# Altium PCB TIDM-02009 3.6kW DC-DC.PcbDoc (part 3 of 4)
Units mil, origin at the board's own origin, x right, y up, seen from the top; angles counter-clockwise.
Board outline 11220.47 x 8463 mil, 4 copper layers (Top Layer, Signal Layer 1, Signal Layer 2, Bottom Layer), stack 109.77 mil thick; 298 components, 250 nets, 959 pads, 2937 vias.
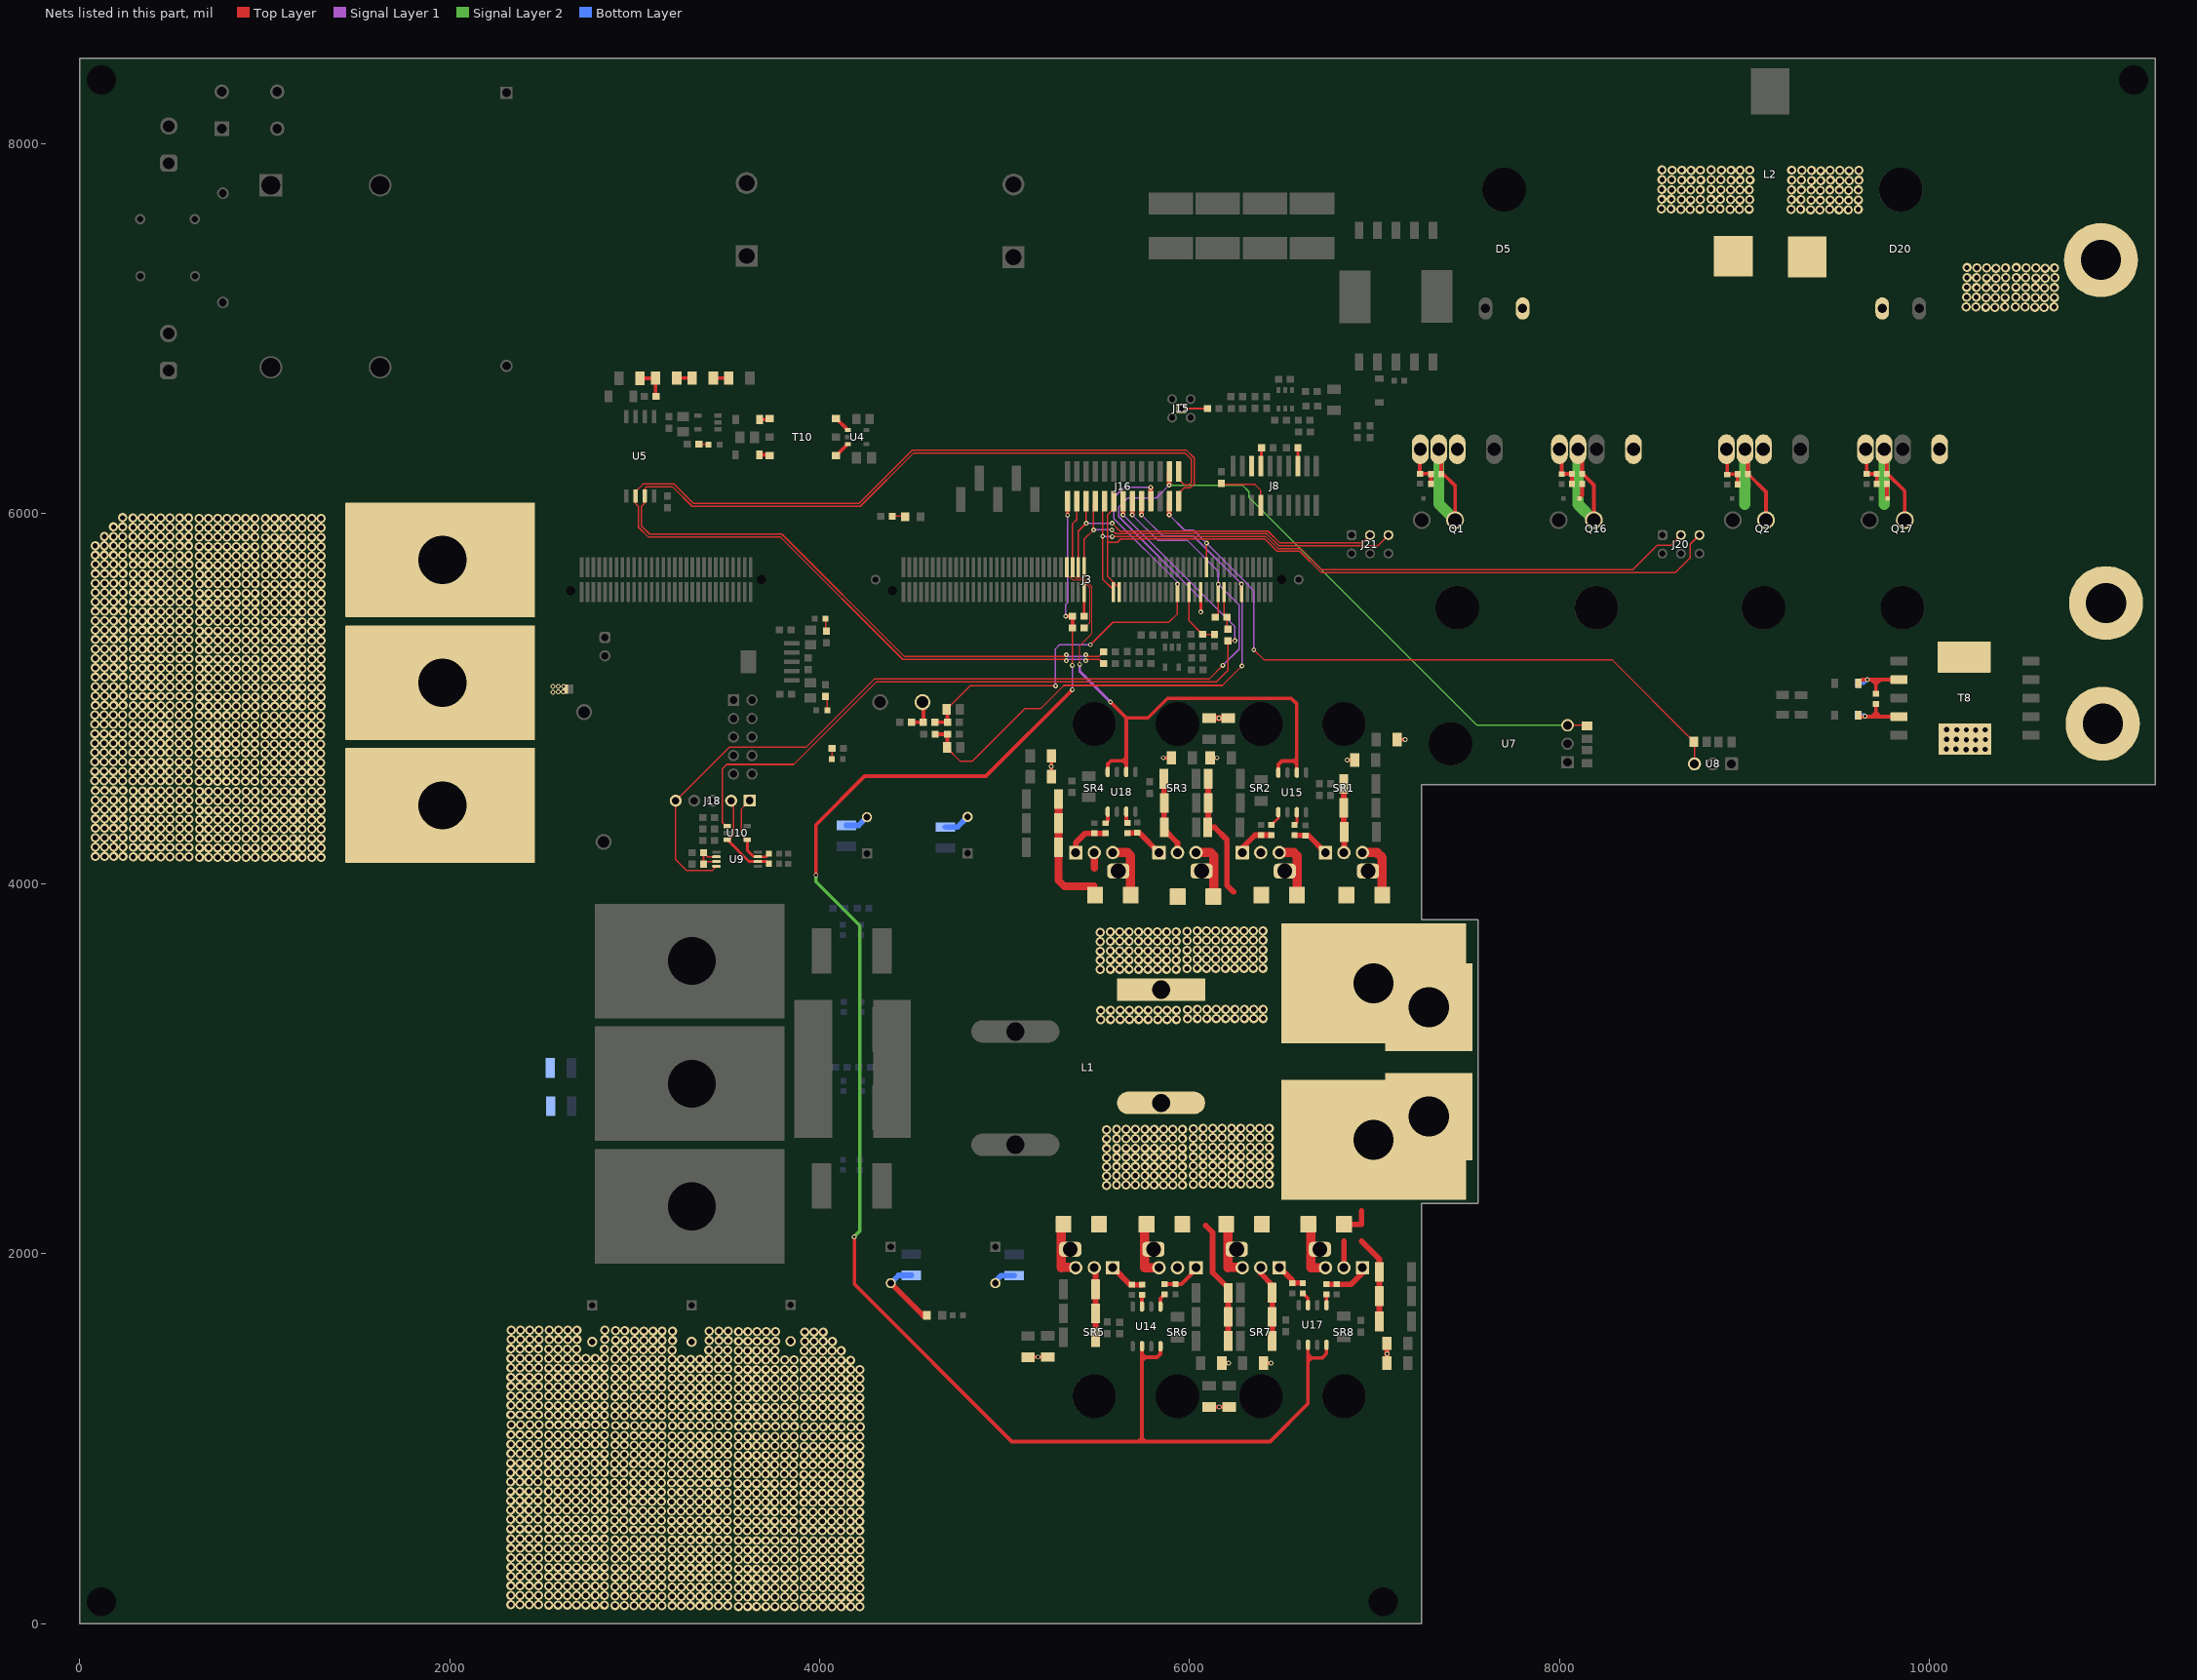
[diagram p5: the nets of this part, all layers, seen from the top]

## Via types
v1: diameter 50, hole 28, Top Layer to Bottom Layer, 2769 vias
v2: diameter 26, hole 12, Top Layer to Bottom Layer, 96 vias
v3: diameter 26, hole 16, Top Layer to Bottom Layer, 49 vias
v4: diameter 36, hole 20, Top Layer to Bottom Layer, 14 vias
v5: diameter 34, hole 16, Top Layer to Bottom Layer, tented both sides, 6 vias
v6: diameter 40, hole 20, Top Layer to Bottom Layer, 2 vias
v7: diameter 50, hole 30, Top Layer to Bottom Layer, 1 vias

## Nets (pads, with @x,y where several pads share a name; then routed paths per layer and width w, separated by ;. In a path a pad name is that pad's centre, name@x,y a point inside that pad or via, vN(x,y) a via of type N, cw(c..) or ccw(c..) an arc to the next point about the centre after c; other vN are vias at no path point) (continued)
NetD5_2: D5.2 D20.1 L2.2 pad.2@10926,7372 T8.11
  other v1: 10354,7116 10620,7116 10304,7117 10570,7117 10407,7118 10673,7118 10198,7119 10250,7119 10464,7119 10516,7119 10356,7168 10622,7168 10306,7169 10572,7169 10409,7170 10675,7170 10200,7171 10252,7171 10466,7171 10518,7171 10356,7222 10622,7222 10254,7223 10306,7223 10408,7223 10520,7223 10572,7223 10674,7223 10200,7225 10466,7225 10358,7274 10624,7274 10308,7275 10574,7275 10411,7276 10677,7276 10202,7277 10254,7277 10468,7277 10520,7277 10358,7328 10624,7328 10256,7329 10308,7329 10410,7329 10522,7329 10574,7329 10676,7329 10202,7331 10468,7331 9407,7643 9561,7643 9357,7644 9511,7644 9460,7645 9614,7645 9251,7646 9303,7646 9409,7695 9563,7695 9359,7696 9513,7696 9462,7697 9616,7697 9253,7698 9305,7698 9409,7749 9563,7749 9307,7750 9359,7750 9461,7750 9513,7750 9615,7750 9253,7752 9411,7801 9565,7801 9361,7802 9515,7802 9464,7803 9618,7803 9255,7804 9307,7804 9411,7855 9565,7855 9309,7856 9361,7856 9463,7856 9515,7856 9617,7856 9255,7858
NetD6_1: D6.1 D7.1 D8.1 D9.1 L1.1 pad.4 R27.1 R28.1 R29.1 R30.1 R31.1 R32.1 R33.1 R34.1 R35.1 R36.1 R37.1 R38.1 SR1.2 SR2.2 SR3.2 SR4.2 | length 2226.5
  Top Layer w30: R33.1@5861.77,4567 5861.77,4437.87 R34.1@5862.64,4437 R35.1@5862.64,4304.73 5862.64,4293.36 5934.48,4221.52 SR3.2@5934.48,4168.79 ; R30.1@6100.44,4566.97 R31.1@6100.44,4436 6100.44,4306.17 R32.1@6099,4304.73 6135.27,4304.73 6202,4238 6202,3992 6238,3956 ; R29.1@6832.81,4539.62 R28.1@6832.81,4409.62 6832.81,4283 R27.1@6836.2,4279.62 6836.2,4170.7 SR1.2@6834.28,4168.79
  Top Layer w40: R38.1@5291.14,4457.45 R37.1@5291.14,4327.45 R36.1@5291.14,4197.45 5291.14,4018.86 5324,3986 5483,3986 ; D9.1@5480.21,3938.79 D9.1@5488.13,3938.79 ; 5484.58,4086 SR4.2@5484.58,4168.79
  other v1: 5519,3264.5 5573,3266.5 5624,3266.5 5675,3266.5 5726,3266.5 5776,3266.5 5827,3266.5 5878,3266.5 5929,3266.5 5988,3269.5 6042,3271.5 6093,3271.5 6144,3271.5 6195,3271.5 6245,3271.5 6296,3271.5 6347,3271.5 6398,3271.5 5519,3314.25 5573,3316.25 5624,3316.25 5675,3316.25 5726,3316.25 5776,3316.25 5827,3316.25 5878,3316.25 5929,3316.25 5988,3319.25 6042,3321.25 6093,3321.25 6144,3321.25 6195,3321.25 6245,3321.25 6296,3321.25 6347,3321.25 6398,3321.25 5517,3536 5571,3538 5622,3538 5673,3538 5724,3538 5774,3538 5825,3538 5876,3538 5927,3538 5986,3541 6040,3543 6091,3543 6142,3543 6193,3543 6243,3543 6294,3543 6345,3543 6396,3543 5517,3585.75 5571,3587.75 5622,3587.75 5673,3587.75 5724,3587.75 5774,3587.75 5825,3587.75 5876,3587.75 5927,3587.75 5986,3590.75 6040,3592.75 6091,3592.75 6142,3592.75 6193,3592.75 6243,3592.75 6294,3592.75 6345,3592.75 6396,3592.75 5517,3635.5 5571,3637.5 5622,3637.5 5673,3637.5 5724,3637.5 5774,3637.5 5825,3637.5 5876,3637.5 5927,3637.5 5986,3640.5 6040,3642.5 6091,3642.5 6142,3642.5 6193,3642.5 6243,3642.5 6294,3642.5 6345,3642.5 6396,3642.5 5517,3687.5 5571,3689.5 5622,3689.5 5673,3689.5 5724,3689.5 5774,3689.5 5825,3689.5 5876,3689.5 5927,3689.5 5986,3692.5 6040,3694.5 6091,3694.5 6142,3694.5 6193,3694.5 6243,3694.5 6294,3694.5 6345,3694.5 6396,3694.5 5517,3737.25 5571,3739.25 5622,3739.25 5673,3739.25 5724,3739.25 5774,3739.25 5825,3739.25 5876,3739.25 5927,3739.25 5986,3742.25 6040,3744.25 6091,3744.25 6142,3744.25 6193,3744.25 6243,3744.25 6294,3744.25 6345,3744.25 6396,3744.25
NetD10_2: D10.2 D11.2 D12.2 D13.2 L1.3 pad.3 R44.1 R45.1 R46.1 R47.1 R48.1 R49.1 R50.1 R51.1 R52.1 R53.1 R54.1 R55.1 SR5.2 SR6.2 SR7.2 SR8.2 | length 2235.2
  Top Layer w30: SR5.2@5485.1,1926.05 5491.52,1919.62 R46.1@5491.52,1807.96 R45.1@5491.52,1677.61 R44.1@5491.52,1547.61 ; 6087,2152 6124.52,2114.48 6124.52,1898.44 6208.34,1814.62 R47.1@6208.34,1788.61 R48.1@6208.34,1658.61 R49.1@6208.34,1528.61 ; SR7.2@6384.9,1926.05 6384.9,1892.5 6446.52,1830.88 R50.1@6446.52,1788.96 R51.1@6446.52,1658.61 R52.1@6446.52,1528.61 ; D13.2@6834.68,2158.79 6929.21,2158.79 6929.21,2231.21 ; SR8.2@6834.8,1924.95 6835.2,1925.35 6835.2,2067.23 ; 6929.73,2067.23 7026.01,1970.95 R53.1@7026.01,1659.07
  other v1: 5551,2369.5 5605,2371.5 5656,2371.5 5707,2371.5 5758,2371.5 5808,2371.5 5859,2371.5 5910,2371.5 5961,2371.5 6020,2374.5 6074,2376.5 6125,2376.5 6176,2376.5 6227,2376.5 6277,2376.5 6328,2376.5 6379,2376.5 6430,2376.5 5551,2419.25 5605,2421.25 5656,2421.25 5707,2421.25 5758,2421.25 5808,2421.25 5859,2421.25 5910,2421.25 5961,2421.25 6020,2424.25 6074,2426.25 6125,2426.25 6176,2426.25 6227,2426.25 6277,2426.25 6328,2426.25 6379,2426.25 6430,2426.25 5551,2469 5605,2471 5656,2471 5707,2471 5758,2471 5808,2471 5859,2471 5910,2471 5961,2471 6020,2474 6074,2476 6125,2476 6176,2476 6227,2476 6277,2476 6328,2476 6379,2476 6430,2476 5551,2518.75 5605,2520.75 5656,2520.75 5707,2520.75 5758,2520.75 5808,2520.75 5859,2520.75 5910,2520.75 5961,2520.75 6020,2523.75 6074,2525.75 6125,2525.75 6176,2525.75 6227,2525.75 6277,2525.75 6328,2525.75 6379,2525.75 6430,2525.75 5551,2568.5 5605,2570.5 5656,2570.5 5707,2570.5 5758,2570.5 5808,2570.5 5859,2570.5 5910,2570.5 5961,2570.5 6020,2573.5 6074,2575.5 6125,2575.5 6176,2575.5 6227,2575.5 6277,2575.5 6328,2575.5 6379,2575.5 6430,2575.5 5551,2620.5 5605,2622.5 5656,2622.5 5707,2622.5 5758,2622.5 5808,2622.5 5859,2622.5 5910,2622.5 5961,2622.5 6020,2625.5 6074,2627.5 6125,2627.5 6176,2627.5 6227,2627.5 6277,2627.5 6328,2627.5 6379,2627.5 6430,2627.5 5551,2670.25 5605,2672.25 5656,2672.25 5707,2672.25 5758,2672.25 5808,2672.25 5859,2672.25 5910,2672.25 5961,2672.25 6020,2675.25 6074,2677.25 6125,2677.25 6176,2677.25 6227,2677.25 6277,2677.25 6328,2677.25 6379,2677.25 6430,2677.25
NetD14_2: D14.2 D15.1 R43.1 T8.4 | length 407.4
  Top Layer w20: D14.2@9615.47,4911 9622.47,4904 9686,4904 ; R43.1@9710,4972.44 9710,4928 ; 9743,4904 9734,4904 ; T8.4@9835.19,4904 9734,4904 ; 9686,4904 9711,4904 ; 9686,4904 9710,4928 ; 9710,4928 9710,4905 9711,4904 ; 9710,4928 9734,4904 ; 9711,4904 9734,4904
  Bottom Layer w20: D15.1@9614.47,4911 9645,4911 v3(9651,4905)
NetD16_2: D16.2 D17.1 R43.2 T8.2 | length 443.2
  Top Layer w20: D16.2@9615.47,5084 9635.47,5104 v3(9663,5104) ; v3@9665,5104 v3(9663,5104) ; R43.2@9710,5027.56 9710,5079 ; 9744,5104 9735,5104 ; T8.2@9835.19,5104 9735,5104 ; v3(9663,5104) 9685,5104 ; 9685,5104 9713,5104 ; 9685,5104 9710,5079 ; 9710,5079 9710,5101 9713,5104 ; 9710,5079 9735,5104 ; 9713,5104 9735,5104
  Bottom Layer w20: D17.1@9615.47,5084 9643,5084 v3(9663,5104)
NetD18_2: D18.2 R69.1 | length 83.8
  Top Layer w20: D18.2@8106.31,6084 8121.56,6099.25 R69.1@8121.56,6161.44
NetD19_2: D19.2 R70.1 | length 78.4
  Top Layer w20: R70.1@9770.12,6161 9770.12,6087.5 D19.2@9773.61,6084
NetD21_2: D21.2 T10.6 | length 55.8
  Top Layer w20: D21.2@3674.47,6318 3726,6318 T10.6@3729,6315
NetD22_2: D22.2 R95.1 | length 70.7
  Top Layer w8: R95.1@4392.5,5987 4460.32,5987 D22.2@4462.32,5985
NetD23_1: D23.1 R75.1 | length 53.1
  Top Layer w8: R75.1@3347,6376 3397.25,6376 D23.1@3399.25,6374
NetD24_1: D24.1 R96.1 | length 57
  Top Layer w8: D24.1@4065.98,4675.03 R96.1@4065.98,4732
NetD25_1: D25.1 R88.1 | length 68.9
  Top Layer w8: D25.1@4032.53,5433 4032.53,5368.97 R88.1@4036,5365.5
NetD26_1: D26.1 R140.1 | length 80.5
  Top Layer w8: R140.1@4032,5013.5 4041.53,5003.98 D26.1@4041.53,4937
NetD27_2: D27.2 T10.4 | length 55.6
  Top Layer w20: D27.2@3675.47,6510 3724,6510 T10.4@3729,6515
NetJ3_18: J3.18 R91.1 R92.1 | length 209.3
  Top Layer w8: J3.18@6186.04,5577.14 6186.04,5456.46 R91.1@6201.5,5441 6201.5,5382 R92.1@6207,5376.5
NetJ3_58: J3.58 R12.1 | length 131.2
  Top Layer w15: R12.1@5430,5446 5430,5577.01 J3.58@5430.13,5577.14
NetJ3_63: J3.63 R87.2 | length 422.3
  Top Layer w6: J3.63@5335.65,5711 5335.65,5674.35 5368,5642 5419,5642 5460.56,5600.44 5460.56,5413.57 R87.2@5429.99,5383
NetJ8_5: J8.5 R16.2 | length 99.2
  Top Layer w15: J8.5@6585,6258 6585.5,6258.5 R16.2@6585.5,6357
NetJ8_13: J8.13 R39.2 | length 100.2
  Top Layer w15: J8.13@6385,6258 6388.01,6261.01 R39.2@6388.01,6357
NetJ8_14: J8.14 R19.1 | length 311.5
  Top Layer w8: R19.1@6171,6164.5 6177.37,6158.13 6353.87,6158.13 6385,6127 J8.14@6385,6045.01
NetJ15_1: J15.1 R59.2 | length 140.9
  Top Layer w10: J15.1@5955,6570 5956,6569 R59.2@6095.5,6569
NetJ18_1: J18.1 R10.1 U9.3 U10.4 | length 442.8
  Top Layer w8: U10.4@3609.13,4237.6 3603.4,4237.6 3576,4265 3576,4403 J18.1@3622,4449
  Top Layer w15: U10.4@3609.13,4237.6 3609.13,4179.83 3640.83,4148.14 3663.86,4148.14 U9.3@3666.2,4145.8 3708.24,4145.8 R10.1@3725.44,4163
NetJ18_2: J18.2 R13.1 U9.2 U10.3 | length 513.6
  Top Layer w8: U10.3@3500.87,4237.6 3510.58,4237.6 3534,4261.02 3534,4437 J18.2@3522,4449
  Top Layer w15: U10.3@3500.87,4237.6 3618.26,4120.2 U9.2@3666.2,4120.2 3712.8,4120.2 R13.1@3725,4108
NetL2_1: L2.1 Q1.2 Q16.1
  other v1: 8706,7645 8972,7645 8656,7646 8922,7646 8759,7647 9025,7647 8550,7648 8602,7648 8816,7648 8868,7648 8708,7697 8974,7697 8658,7698 8924,7698 8761,7699 9027,7699 8552,7700 8604,7700 8818,7700 8870,7700 8708,7751 8974,7751 8606,7752 8658,7752 8760,7752 8872,7752 8924,7752 9026,7752 8552,7754 8818,7754 8710,7803 8976,7803 8660,7804 8926,7804 8763,7805 9029,7805 8554,7806 8606,7806 8820,7806 8872,7806 8710,7857 8976,7857 8608,7858 8660,7858 8762,7858 8874,7858 8926,7858 9028,7858 8554,7860 8820,7860
NetQ1_4: Q1.4 R21.2 R23.2 R25.2 | length 247.8
  Top Layer w20: Q1.4@7247,6348.89 7245,6346.89 R21.2@7245,6217.12 7301.32,6217.12 R25.2@7304.44,6214 ; R23.2@7304.44,6161 R25.2@7304.44,6214 ; R25.2@7305.44,6215 R25.2@7304.44,6214
NetQ2_2: pad.1@10954,5518 Q2.2 Q17.1
NetQ2_4: Q2.4 R22.2 R24.2 R26.2 | length 251.5
  Top Layer w20: Q2.4@8901.89,6348.89 8906,6344.78 R22.2@8906,6212 8909,6215 R26.2@8962.44,6215 8961.88,6214.44 R24.2@8961.88,6160
NetQ16_4: Q16.4 R64.2 R69.2 R71.2 | length 249.7
  Top Layer w20: Q16.4@7999.44,6348.89 8011,6337.34 R64.2@8011,6214.56 8012.44,6216 R71.2@8066.44,6216 R69.2@8066.44,6161.44
NetQ17_4: Q17.4 R65.2 R70.2 R72.2 | length 244.9
  Top Layer w20: Q17.4@9654.33,6348.89 9660,6343.23 R65.2@9660,6216.56 9660.56,6216 R72.2@9715,6216 R70.2@9715,6161
NetR40_1: R40.1 R57.2 TP3.1 | length 176.6
  Top Layer w20: R40.1@4495.5,4873 R57.2@4561.01,4873 4561.01,4976.99 TP3.1@4556,4982
NetR76_2: R76.2 R77.1 | length 83.8
  Top Layer w20: R77.1@3425.17,6734 R76.2@3509,6734
NetR77_2: R77.2 R78.1 | length 83.8
  Top Layer w20: R78.1@3227.17,6734 R77.2@3311,6734
NetR78_2: R78.2 R79.1 R80.2 | length 184.8
  Top Layer w20: R80.2@3029.09,6733 3112,6733 R78.2@3113,6734 3113,6638.5 R79.1@3116.5,6635
NetR89_1: R89.1 R90.2 U9.6 U9.7 | length 215.7
  Top Layer w8: U9.7@3441.8,4120.2 3386.7,4120.2 R90.2@3372.5,4106 R89.1@3372.5,4168 3394.7,4145.8 U9.6@3441.8,4145.8
NetR152_1: R152.1 U14.7 | length 63
  Top Layer w20: U14.7@5742.47,1714.35 5742.47,1775.26 R152.1@5743.92,1776.72
NetR153_1: R153.1 U15.7 | length 74.3
  Top Layer w15: R153.1@6567.19,4316.98 6579.39,4329.18 U15.7@6579.39,4386.23
NetR155_1: R155.1 U14.5 | length 74.1
  Top Layer w20: U14.5@5842.47,1714.35 5842.47,1758.06 R155.1@5863.92,1779.52
NetR156_1: R156.1 U15.5 | length 83.7
  Top Layer w15: R156.1@6441.7,4318.16 6479.39,4355.86 U15.5@6479.39,4386.23
NetR168_1: R168.1 U17.7 | length 76.6
  Top Layer w20: R168.1@6611.76,1786.44 6639.91,1758.29 U17.7@6639.91,1721.52
NetR169_1: R169.1 U18.7 | length 63.5
  Top Layer w15: R169.1@5657.42,4335.7 R169.1@5664,4329.12
  Top Layer w20: R169.1@5657.42,4335.7 U18.7@5657.42,4389.88
NetR170_1: R170.1 U17.5 | length 58.5
  Top Layer w20: R170.1@6738.74,1779.55 6739.91,1778.38 U17.5@6739.91,1721.52
NetR171_1: R171.1 U18.5 | length 67.5
  Top Layer w15: R171.1@5545.22,4327.45 R171.1@5557.42,4339.65
  Top Layer w20: R171.1@5557.42,4339.65 U18.5@5557.42,4389.88
NetT6_1: pad.2@10936,4865 T8.12
  other v1: 10247,4725 10197,4726 10300,4727 10091,4728 10143,4728 10249,4777 10199,4778 10302,4779 10093,4780 10145,4780 10249,4831 10147,4832 10199,4832 10301,4832 10093,4834
NetT10_1: T10.1 U4.3 | length 89.7
  Top Layer w20: T10.1@4089,6315 4090.2,6315 U4.3@4152.8,6377.6
NetT10_3: T10.3 U4.1 | length 89.7
  Top Layer w20: T10.3@4089,6515 4090.2,6515 U4.1@4152.8,6452.4
nTGTRST: J8.15
PGND: C14.2 C15.2 C16.1 C17.1 C18.1 C19.1 C20.1 C21.1 C22.1 C23.1 C24.2 C25.2 C26.2 C27.2 C28.2 C29.2 C30.2 C31.1 C32.1 C33.1 C34.1 C35.1 C36.1 C37.1 C38.1 C44.2 C71.2 C72.2 C86.2 D1.1 D6.2 D7.2 D8.2 D9.2 D10.1 D11.1 D12.1 D13.1 NT1.1 pad.1@1961.56,4423.45 pad.1@1961.56,5086.97 pad.1@1961.56,5750.49 pad.5 SR1.3 SR2.3 SR3.3 SR4.3 SR5.3 SR6.3 SR7.3 SR8.3 T2.1 T3.1 T4.1 | length 4173.7
  Top Layer w20: C31.1@5126.52,1440.27 5127.61,1441.35 v3(5180.56,1441.35) C35.1@5233.52,1441.35 ; C23.1@5252.7,4578.72 v3(5252.7,4634.96) C19.1@5252.7,4691.2 ; v3(5858.21,4680.79) C22.1@5901.3,4680.79 ; C32.1@6105.73,1171.14 v3(6159.82,1171.14) C37.1@6213.91,1171.14 ; C21.1@6111.33,4680.79 v3(6148.79,4680.79) ; C36.1@6174.08,1408.23 v3(6211.73,1408.23) ; C33.1@6399.87,1408.23 v3(6439.73,1408.23) ; v3(6850.79,4668.79) C20.1@6892.22,4668.79 ; C16.1@7122.21,4778.79 v3(7164.79,4778.79)
  Top Layer w30: C27.2@4384.39,1840.69 4558.08,1667 D1.1@4580.32,1667 ; C18.1@6105,4895.09 C17.1@6209,4895.09 ; C38.1@7066.05,1407.69 C34.1@7066.05,1514.69
  Top Layer w50: D10.1@5305.85,2146.51 D10.1@5306.37,2147.03 ; D10.1@5318.12,2158.79 D10.1@5306.37,2147.03 ; SR5.3@5385.1,1926.05 5307.47,1926.05 5306.37,1924.94 D10.1@5306.37,2147.03 ; SR4.3@5584.58,4168.79 5663.33,4168.79 5681.04,4151.08 D9.2@5681.04,3938.79 ; D11.1@5766.95,2158.79 5755.74,2147.58 5756.26,2147.06 5756.26,1924.94 5757.21,1924 SR6.3@5835,1924 ; SR3.3@6033.79,4168.79 SR3.3@6034.48,4168.79 6113.22,4168.79 6130.94,4151.07 D8.2@6130.94,3938.79 ; D12.1@6197.93,2158.79 6206.16,2150.57 6206.16,1924.94 6207.26,1926.05 SR7.3@6284.9,1926.05 ; SR2.3@6484.38,4168.79 6563.12,4168.79 6580.85,4151.06 D7.2@6580.85,3938.79 ; D13.1@6641.77,2158.79 6656.05,2144.5 6656.05,1924.95 SR8.3@6734.8,1924.95 ; SR1.3@6934.28,4168.79 7013.01,4168.79 7040.52,4141.28 D6.2@7040.52,3938.79
  Bottom Layer w20: T2.1@1923,4384.89 T2.1@1961.56,4423.45
  Bottom Layer w30: C86.2@4144,4316 4211.53,4316 C25.2@4255.61,4360.08 ; C27.2@4384.39,1840.69 4426.62,1882.91 C30.2@4496,1882.91 ; C28.2@4680,4307 4745.27,4307 C24.2@4800.06,4361.79 ; C26.2@4940.69,1841.94 4980.67,1881.91 C29.2@5052,1881.91
  other v1: 3917.25,92 3967,92 4016.75,92 4066.5,92 4116.25,92 4168.25,92 4218,92 3560.25,93 3610,93 3659.75,93 3709.5,93 3759.25,93 3811.25,93 3861,93 3202.25,96 3252,96 3301.75,96 3351.5,96 3401.25,96 3453.25,96 3503,96 2997.25,97 3047,97 3096.75,97 3146.5,97 2894.25,98 2944,98 2536.25,101 2586,101 2635.75,101 2685.5,101 2735.25,101 2787.25,101 2837,101 2331.25,102 2381,102 2430.75,102 2480.5,102 3917.25,143 3967,143 4016.75,143 4066.5,143 4116.25,143 4168.25,143 4218,143 3560.25,144 3610,144 3659.75,144 3709.5,144 3759.25,144 3811.25,144 3861,144 3202.25,147 3252,147 3301.75,147 3351.5,147 3401.25,147 3453.25,147 3503,147 2997.25,148 3047,148 3096.75,148 3146.5,148 2894.25,149 2944,149 2536.25,152 2586,152 2635.75,152 2685.5,152 2735.25,152 2787.25,152 2837,152 2331.25,153 2381,153 2430.75,153 2480.5,153 3917.25,194 3967,194 4016.75,194 4066.5,194 4116.25,194 4168.25,194 4218,194 3560.25,195 3610,195 3659.75,195 3709.5,195 3759.25,195 3811.25,195 3861,195 3202.25,198 3252,198 3301.75,198 3351.5,198 3401.25,198 3453.25,198 3503,198 2997.25,199 3047,199 3096.75,199 3146.5,199 2894.25,200 2944,200 2536.25,203 2586,203 2635.75,203 2685.5,203 2735.25,203 2787.25,203 2837,203 2331.25,204 2381,204 2430.75,204 2480.5,204 3917.25,245 3967,245 4016.75,245 4066.5,245 4116.25,245 4168.25,245 4218,245 3560.25,246 3610,246 3659.75,246 3709.5,246 3759.25,246 3811.25,246 3861,246 3202.25,249 3252,249 3301.75,249 3351.5,249 3401.25,249 3453.25,249 3503,249 2997.25,250 3047,250 3096.75,250 3146.5,250 2894.25,251 2944,251 2536.25,254 2586,254 2635.75,254 2685.5,254 2735.25,254 2787.25,254 2837,254 2331.25,255 2381,255 2430.75,255 2480.5,255 3917.25,295 3967,295 4016.75,295 4066.5,295 4116.25,295 4168.25,295 4218,295 3560.25,296 3610,296 3659.75,296 3709.5,296 3759.25,296 3811.25,296 3861,296 3202.25,299 3252,299 3301.75,299 3351.5,299 3401.25,299 3453.25,299 3503,299 2997.25,300 3047,300 3096.75,300 3146.5,300 2894.25,301 2944,301 2536.25,304 2586,304 2635.75,304 2685.5,304 2735.25,304 2787.25,304 2837,304 2331.25,305 2381,305 2430.75,305 2480.5,305 3917.25,346 3967,346 4016.75,346 4066.5,346 4116.25,346 4168.25,346 4218,346 3560.25,347 3610,347 3659.75,347 3709.5,347 3759.25,347 3811.25,347 3861,347 3202.25,350 3252,350 3301.75,350 3351.5,350 3401.25,350 3453.25,350 3503,350 2997.25,351 3047,351 3096.75,351 3146.5,351 2894.25,352 2944,352 2536.25,355 2586,355 2635.75,355 2685.5,355 2735.25,355 2787.25,355 2837,355 2331.25,356 2381,356 2430.75,356 2480.5,356 3917.25,397 3967,397 4016.75,397 4066.5,397 4116.25,397 4168.25,397 4218,397 3560.25,398 3610,398 3659.75,398 3709.5,398 3759.25,398 3811.25,398 3861,398 3202.25,401 3252,401 3301.75,401 3351.5,401 3401.25,401 3453.25,401 3503,401 2997.25,402 3047,402 3096.75,402 3146.5,402 2894.25,403 2944,403 2536.25,406 2586,406 2635.75,406 2685.5,406 2735.25,406 2787.25,406 2837,406 2331.25,407 2381,407 2430.75,407 2480.5,407 3917.25,448 3967,448 4016.75,448 4066.5,448 4116.25,448 4168.25,448 4218,448 3560.25,449 3610,449 3659.75,449 3709.5,449 3759.25,449 3811.25,449 3861,449 3202.25,452 3252,452 3301.75,452 3351.5,452 3401.25,452 3453.25,452 3503,452 2997.25,453 3047,453 3096.75,453 3146.5,453 2894.25,454 2944,454 2536.25,457 2586,457 2635.75,457 2685.5,457 2735.25,457 2787.25,457 2837,457 2331.25,458 2381,458 2430.75,458 2480.5,458 3915.25,502 3965,502 4014.75,502 4064.5,502 4114.25,502 4166.25,502 4216,502 3558.25,503 3608,503 3657.75,503 3707.5,503 3757.25,503 3809.25,503 3859,503 3200.25,506 3250,506 3299.75,506 3349.5,506 3399.25,506 3451.25,506 3501,506 2995.25,507 3045,507 3094.75,507 3144.5,507 2892.25,508 2942,508 2534.25,511 2584,511 2633.75,511 2683.5,511 2733.25,511 2785.25,511 2835,511 2329.25,512 2379,512 2428.75,512 2478.5,512 3915.25,553 3965,553 4014.75,553 4064.5,553 4114.25,553 4166.25,553 4216,553 3558.25,554 3608,554 3657.75,554 3707.5,554 3757.25,554 3809.25,554 3859,554 3200.25,557 3250,557 3299.75,557 3349.5,557 3399.25,557 3451.25,557 3501,557 2995.25,558 3045,558 3094.75,558 3144.5,558 2892.25,559 2942,559 2534.25,562 2584,562 2633.75,562 2683.5,562 2733.25,562 2785.25,562 2835,562 2329.25,563 2379,563 2428.75,563 2478.5,563 3915.25,604 3965,604 4014.75,604 4064.5,604 4114.25,604 4166.25,604 4216,604 3558.25,605 3608,605 3657.75,605 3707.5,605 3757.25,605 3809.25,605 3859,605 3200.25,608 3250,608 3299.75,608 3349.5,608 3399.25,608 3451.25,608 3501,608 2995.25,609 3045,609 3094.75,609 3144.5,609 2892.25,610 2942,610 2534.25,613 2584,613 2633.75,613 2683.5,613 2733.25,613 2785.25,613 2835,613 2329.25,614 2379,614 2428.75,614 2478.5,614 3915.25,655 3965,655 4014.75,655 4064.5,655 4114.25,655 4166.25,655 4216,655 3558.25,656 3608,656 3657.75,656 3707.5,656 3757.25,656 3809.25,656 3859,656 3200.25,659 3250,659 3299.75,659 3349.5,659 3399.25,659 3451.25,659 3501,659 2995.25,660 3045,660 3094.75,660 3144.5,660 2892.25,661 2942,661 2534.25,664 2584,664 2633.75,664 2683.5,664 2733.25,664 2785.25,664 2835,664 2329.25,665 2379,665 2428.75,665 2478.5,665 3915.25,705 3965,705 4014.75,705 4064.5,705 4114.25,705 4166.25,705 4216,705 3558.25,706 3608,706 3657.75,706 3707.5,706 3757.25,706 3809.25,706 3859,706 3200.25,709 3299.75,709 3349.5,709 3399.25,709 3451.25,709 3501,709 2995.25,710 3045,710 3094.75,710 3144.5,710 3251,710 2892.25,711 2942,711 2534.25,714 2633.75,714 2683.5,714 2733.25,714 2785.25,714 2835,714 2329.25,715 2379,715 2428.75,715 2478.5,715 2585,715 3915.25,756 3965,756 4014.75,756 4064.5,756 4114.25,756 4166.25,756 4216,756 3558.25,757 3608,757 3657.75,757 3707.5,757 3757.25,757 3809.25,757 3859,757 3200.25,760 3250,760 3299.75,760 3349.5,760 3399.25,760 3451.25,760 3501,760 2995.25,761 3045,761 3094.75,761 3144.5,761 2892.25,762 2942,762 2534.25,765 2584,765 2633.75,765 2683.5,765 2733.25,765 2785.25,765 2835,765 2329.25,766 2379,766 2428.75,766 2478.5,766 3915.25,807 3965,807 4014.75,807 4064.5,807 4114.25,807 4166.25,807 4216,807 3558.25,808 3608,808 3657.75,808 3707.5,808 3757.25,808 3809.25,808 3859,808 3200.25,811 3250,811 3299.75,811 3349.5,811 3399.25,811 3451.25,811 3501,811 2995.25,812 3045,812 3094.75,812 3144.5,812 2892.25,813 2942,813 2534.25,816 2584,816 2633.75,816 2683.5,816 2733.25,816 2785.25,816 2835,816 2329.25,817 2379,817 2428.75,817 2478.5,817 3915.25,858 3965,858 4014.75,858 4064.5,858 4114.25,858 4166.25,858 4216,858 3558.25,859 3608,859 3657.75,859 3707.5,859 3757.25,859 3809.25,859 3859,859 3200.25,862 3250,862 3299.75,862 3349.5,862 3399.25,862 3451.25,862 3501,862 2995.25,863 3045,863 3094.75,863 3144.5,863 2892.25,864 2942,864 2534.25,867 2584,867 2633.75,867 2683.5,867 2733.25,867 2785.25,867 2835,867 2329.25,868 2379,868 2428.75,868 2478.5,868 3917.25,909 3967,909 4016.75,909 4066.5,909 4116.25,909 4168.25,909 4218,909 3560.25,910 3610,910 3659.75,910 3709.5,910 3759.25,910 3811.25,910 3861,910 3202.25,913 3252,913 3301.75,913 3351.5,913 3401.25,913 3453.25,913 3503,913 2997.25,914 3047,914 3096.75,914 3146.5,914 2894.25,915 2944,915 2536.25,918 2586,918 2635.75,918 2685.5,918 2735.25,918 2787.25,918 2837,918 2331.25,919 2381,919 2430.75,919 2480.5,919 3917.25,960 3967,960 4016.75,960 4066.5,960 4116.25,960 4168.25,960 4218,960 3560.25,961 3610,961 3659.75,961 3709.5,961 3759.25,961 3811.25,961 3861,961 3202.25,964 3252,964 3301.75,964 3351.5,964 3401.25,964 3453.25,964 3503,964 2997.25,965 3047,965 3096.75,965 3146.5,965 2894.25,966 2944,966 2536.25,969 2586,969 2635.75,969 2685.5,969 2735.25,969 2787.25,969 2837,969 2331.25,970 2381,970 2430.75,970 2480.5,970 3917.25,1011 3967,1011 4016.75,1011 4066.5,1011 4116.25,1011 4168.25,1011 4218,1011 3560.25,1012 3610,1012 3659.75,1012 3709.5,1012 3759.25,1012 3811.25,1012 3861,1012 3202.25,1015 3252,1015 3301.75,1015 3351.5,1015 3401.25,1015 3453.25,1015 3503,1015 2997.25,1016 3047,1016 3096.75,1016 3146.5,1016 2894.25,1017 2944,1017 2536.25,1020 2586,1020 2635.75,1020 2685.5,1020 2735.25,1020 2787.25,1020 2837,1020 2331.25,1021 2381,1021 2430.75,1021 2480.5,1021 3919.25,1065 3969,1065 4018.75,1065 4068.5,1065 4118.25,1065 4170.25,1065 4220,1065 3562.25,1066 3612,1066 3661.75,1066 3711.5,1066 3761.25,1066 3813.25,1066 3863,1066 3204.25,1069 3254,1069 3303.75,1069 3353.5,1069 3403.25,1069 3455.25,1069 3505,1069 2999.25,1070 3049,1070 3098.75,1070 3148.5,1070 2896.25,1071 2946,1071 2538.25,1074 2588,1074 2637.75,1074 2687.5,1074 2737.25,1074 2789.25,1074 2839,1074 2333.25,1075 2383,1075 2432.75,1075 2482.5,1075 3917.25,1119 3967,1119 4016.75,1119 4066.5,1119 4116.25,1119 4168.25,1119 4218,1119 3560.25,1120 3610,1120 3659.75,1120 3709.5,1120 3759.25,1120 3811.25,1120 3861,1120 3202.25,1123 3252,1123 3301.75,1123 3351.5,1123 3401.25,1123 3453.25,1123 3503,1123 2997.25,1124 3047,1124 3096.75,1124 3146.5,1124 2894.25,1125 2944,1125 2536.25,1128 2586,1128 2635.75,1128 2685.5,1128 2735.25,1128 2787.25,1128 2837,1128 2331.25,1129 2381,1129 2430.75,1129 2480.5,1129 3917.25,1170 3967,1170 4016.75,1170 4066.5,1170 4116.25,1170 4168.25,1170 4218,1170 3560.25,1171 3610,1171 3659.75,1171 3709.5,1171 3759.25,1171 3811.25,1171 3861,1171 3202.25,1174 3252,1174 3301.75,1174 3351.5,1174 3401.25,1174 3453.25,1174 3503,1174 2997.25,1175 3047,1175 3096.75,1175 3146.5,1175 2894.25,1176 2944,1176 2536.25,1179 2586,1179 2635.75,1179 2685.5,1179 2735.25,1179 2787.25,1179 2837,1179 2331.25,1180 2381,1180 2430.75,1180 2480.5,1180 3917.25,1221 3967,1221 4016.75,1221 4066.5,1221 4116.25,1221 4168.25,1221 4218,1221 3560.25,1222 3610,1222 3659.75,1222 3709.5,1222 3759.25,1222 3811.25,1222 3861,1222 3202.25,1225 3252,1225 3301.75,1225 3351.5,1225 3401.25,1225 3453.25,1225 3503,1225 2997.25,1226 3047,1226 3096.75,1226 3146.5,1226 2894.25,1227 2944,1227 2536.25,1230 2586,1230 2635.75,1230 2685.5,1230 2735.25,1230 2787.25,1230 2837,1230 2331.25,1231 2381,1231 2430.75,1231 2480.5,1231 3917.25,1272 3967,1272 4016.75,1272 4066.5,1272 4116.25,1272 4168.25,1272 4218,1272 3560.25,1273 3610,1273 3659.75,1273 3709.5,1273 3759.25,1273 3811.25,1273 3861,1273 3202.25,1276 3252,1276 3301.75,1276 3351.5,1276 3401.25,1276 3453.25,1276 3503,1276 2997.25,1277 3047,1277 3096.75,1277 3146.5,1277 2894.25,1278 2944,1278 2536.25,1281 2586,1281 2635.75,1281 2685.5,1281 2735.25,1281 2787.25,1281 2837,1281 2331.25,1282 2381,1282 2430.75,1282 2480.5,1282 3917.25,1322 3967,1322 4016.75,1322 4066.5,1322 4116.25,1322 4168.25,1322 4218,1322 3560.25,1323 3610,1323 3659.75,1323 3709.5,1323 3759.25,1323 3811.25,1323 3861,1323 3202.25,1326 3301.75,1326 3351.5,1326 3401.25,1326 3453.25,1326 3503,1326 2997.25,1327 3047,1327 3096.75,1327 3146.5,1327 3253,1327 2894.25,1328 2944,1328 2536.25,1331 2635.75,1331 2685.5,1331 2735.25,1331 2787.25,1331 2837,1331 2331.25,1332 2381,1332 2430.75,1332 2480.5,1332 2587,1332 3917.25,1373 3967,1373 4016.75,1373 4066.5,1373 4116.25,1373 4168.25,1373 4218,1373 3560.25,1374 3610,1374 3659.75,1374 3709.5,1374 3759.25,1374 3811.25,1374 3861,1374 3202.25,1377 3252,1377 3301.75,1377 3351.5,1377 3401.25,1377 3453.25,1377 3503,1377 2997.25,1378 3047,1378 3096.75,1378 3146.5,1378 2894.25,1379 2944,1379 2536.25,1382 2586,1382 2635.75,1382 2685.5,1382 2735.25,1382 2787.25,1382 2837,1382 2331.25,1383 2381,1383 2430.75,1383 2480.5,1383 3917.25,1424 3967,1424 4016.75,1424 4066.5,1424 4116.25,1424 4168.25,1424 3560.25,1425 3610,1425 3659.75,1425 3709.5,1425 3759.25,1425 3811.25,1425 3861,1425 3202.25,1428 3252,1428 3301.75,1428 3351.5,1428 3401.25,1428 3453.25,1428 3503,1428 2997.25,1429 3047,1429 3096.75,1429 3146.5,1429 2894.25,1430 2944,1430 2536.25,1433 2586,1433 2635.75,1433 2685.5,1433 2735.25,1433 2787.25,1433 2837,1433 2331.25,1434 2381,1434 2430.75,1434 2480.5,1434 3917.25,1475 3967,1475 4016.75,1475 4066.5,1475 4116.25,1475 3560.25,1476 3610,1476 3659.75,1476 3709.5,1476 3759.25,1476 3202.25,1479 3401.25,1479 3453.25,1479 3503,1479 2997.25,1480 3047,1480 3096.75,1480 3146.5,1480 2894.25,1481 2944,1481 2536.25,1484 2586,1484 2635.75,1484 2685.5,1484 2837,1484 2331.25,1485 2381,1485 2430.75,1485 2480.5,1485 3919.25,1526 3969,1526 4018.75,1526 4068.5,1526 3562.25,1527 3612,1527 3661.75,1527 3711.5,1527 3761.25,1527 3204.25,1530 3403.25,1530 3455.25,1530 3505,1530 2999.25,1531 3049,1531 3098.75,1531 3148.5,1531 2896.25,1532 2946,1532 2538.25,1535 2588,1535 2637.75,1535 2687.5,1535 2839,1535 2333.25,1536 2383,1536 2432.75,1536 2482.5,1536 3919.25,1577 3969,1577 4018.75,1577 3562.25,1578 3612,1578 3661.75,1578 3711.5,1578 3761.25,1578 3204.25,1581 3403.25,1581 3455.25,1581 3505,1581 2999.25,1582 3049,1582 3098.75,1582 3148.5,1582 2896.25,1583 2946,1583 2538.25,1586 2588,1586 2637.75,1586 2687.5,1586 2839,1586 2333.25,1587 2383,1587 2432.75,1587 2482.5,1587 1004.25,4142 1054,4142 1103.75,4142 1153.5,4142 1203.25,4142 1255.25,4142 1305,4142 647.25,4143 697,4143 746.75,4143 796.5,4143 846.25,4143 898.25,4143 948,4143 289.25,4146 339,4146 388.75,4146 438.5,4146 488.25,4146 540.25,4146 590,4146 84.25,4147 134,4147 183.75,4147 233.5,4147 1004.25,4193 1054,4193 1103.75,4193 1153.5,4193 1203.25,4193 1255.25,4193 1305,4193 647.25,4194 697,4194 746.75,4194 796.5,4194 846.25,4194 898.25,4194 948,4194 289.25,4197 339,4197 388.75,4197 438.5,4197 488.25,4197 540.25,4197 590,4197 84.25,4198 134,4198 183.75,4198 233.5,4198 1004.25,4244 1054,4244 1103.75,4244 1153.5,4244 1203.25,4244 1255.25,4244 1305,4244 647.25,4245 697,4245 746.75,4245 796.5,4245 846.25,4245 898.25,4245 948,4245 289.25,4248 339,4248 388.75,4248 438.5,4248 488.25,4248 540.25,4248 590,4248 84.25,4249 134,4249 183.75,4249 233.5,4249 1004.25,4295 1054,4295 1103.75,4295 1153.5,4295 1203.25,4295 1255.25,4295 1305,4295 647.25,4296 697,4296 746.75,4296 796.5,4296 846.25,4296 898.25,4296 948,4296 289.25,4299 339,4299 388.75,4299 438.5,4299 488.25,4299 540.25,4299 590,4299 84.25,4300 134,4300 183.75,4300 233.5,4300 1004.25,4345 1054,4345 1103.75,4345 1153.5,4345 1203.25,4345 1255.25,4345 1305,4345 647.25,4346 697,4346 746.75,4346 796.5,4346 846.25,4346 898.25,4346 948,4346 289.25,4349 339,4349 388.75,4349 438.5,4349 488.25,4349 540.25,4349 590,4349 84.25,4350 134,4350 183.75,4350 233.5,4350 1004.25,4396 1054,4396 1103.75,4396 1153.5,4396 1203.25,4396 1255.25,4396 1305,4396 647.25,4397 697,4397 746.75,4397 796.5,4397 846.25,4397 898.25,4397 948,4397 289.25,4400 339,4400 388.75,4400 438.5,4400 488.25,4400 540.25,4400 590,4400 84.25,4401 134,4401 183.75,4401 233.5,4401 1004.25,4447 1054,4447 1103.75,4447 1153.5,4447 1203.25,4447 1255.25,4447 1305,4447 647.25,4448 697,4448 746.75,4448 796.5,4448 846.25,4448 898.25,4448 948,4448 289.25,4451 339,4451 388.75,4451 438.5,4451 488.25,4451 540.25,4451 590,4451 84.25,4452 134,4452 183.75,4452 233.5,4452 1004.25,4498 1054,4498 1103.75,4498 1153.5,4498 1203.25,4498 1255.25,4498 1305,4498 647.25,4499 697,4499 746.75,4499 796.5,4499 846.25,4499 898.25,4499 948,4499 289.25,4502 339,4502 388.75,4502 438.5,4502 488.25,4502 540.25,4502 590,4502 84.25,4503 134,4503 183.75,4503 233.5,4503 1002.25,4552 1052,4552 1101.75,4552 1151.5,4552 1201.25,4552 1253.25,4552 1303,4552 645.25,4553 695,4553 744.75,4553 794.5,4553 844.25,4553 896.25,4553 946,4553 287.25,4556 337,4556 386.75,4556 436.5,4556 486.25,4556 538.25,4556 588,4556 82.25,4557 132,4557 181.75,4557 231.5,4557 1002.25,4603 1052,4603 1101.75,4603 1151.5,4603 1201.25,4603 1253.25,4603 1303,4603 645.25,4604 695,4604 744.75,4604 794.5,4604 844.25,4604 896.25,4604 946,4604 287.25,4607 337,4607 386.75,4607 436.5,4607 486.25,4607 538.25,4607 588,4607 82.25,4608 132,4608 181.75,4608 231.5,4608 1002.25,4654 1052,4654 1101.75,4654 1151.5,4654 1201.25,4654 1253.25,4654 1303,4654 645.25,4655 695,4655 744.75,4655 794.5,4655 844.25,4655 896.25,4655 946,4655 287.25,4658 337,4658 386.75,4658 436.5,4658 486.25,4658 538.25,4658 588,4658 82.25,4659 132,4659 181.75,4659 231.5,4659 1002.25,4705 1052,4705 1101.75,4705 1151.5,4705 1201.25,4705 1253.25,4705 1303,4705 645.25,4706 695,4706 744.75,4706 794.5,4706 844.25,4706 896.25,4706 946,4706 287.25,4709 337,4709 386.75,4709 436.5,4709 486.25,4709 538.25,4709 588,4709 82.25,4710 132,4710 181.75,4710 231.5,4710 1002.25,4755 1052,4755 1101.75,4755 1151.5,4755 1201.25,4755 1253.25,4755 1303,4755 645.25,4756 695,4756 744.75,4756 794.5,4756 844.25,4756 896.25,4756 946,4756 287.25,4759 337,4759 386.75,4759 436.5,4759 486.25,4759 538.25,4759 588,4759 82.25,4760 132,4760 181.75,4760 231.5,4760 1002.25,4806 1052,4806 1101.75,4806 1151.5,4806 1201.25,4806 1253.25,4806 1303,4806 645.25,4807 695,4807 744.75,4807 794.5,4807 844.25,4807 896.25,4807 946,4807 287.25,4810 337,4810 386.75,4810 436.5,4810 486.25,4810 538.25,4810 588,4810 82.25,4811 132,4811 181.75,4811 231.5,4811 1002.25,4857 1052,4857 1101.75,4857 1151.5,4857 1201.25,4857 1253.25,4857 1303,4857 645.25,4858 695,4858 744.75,4858 794.5,4858 844.25,4858 896.25,4858 946,4858 287.25,4861 337,4861 386.75,4861 436.5,4861 486.25,4861 538.25,4861 588,4861 82.25,4862 132,4862 181.75,4862 231.5,4862 1002.25,4908 1052,4908 1101.75,4908 1151.5,4908 1201.25,4908 1253.25,4908 1303,4908 645.25,4909 695,4909 744.75,4909 794.5,4909 844.25,4909 896.25,4909 946,4909 287.25,4912 337,4912 386.75,4912 436.5,4912 486.25,4912 538.25,4912 588,4912 82.25,4913 132,4913 181.75,4913 231.5,4913 1004.25,4959 1054,4959 1103.75,4959 1153.5,4959 1203.25,4959 1255.25,4959 1305,4959 647.25,4960 697,4960 746.75,4960 796.5,4960 846.25,4960 898.25,4960 948,4960 289.25,4963 339,4963 388.75,4963 438.5,4963 488.25,4963 540.25,4963 590,4963 84.25,4964 134,4964 183.75,4964 233.5,4964 1004.25,5010 1054,5010 1103.75,5010 1153.5,5010 1203.25,5010 1255.25,5010 1305,5010 647.25,5011 697,5011 746.75,5011 796.5,5011 846.25,5011 898.25,5011 948,5011 289.25,5014 339,5014 388.75,5014 438.5,5014 488.25,5014 540.25,5014 590,5014 84.25,5015 134,5015 183.75,5015 233.5,5015 1004.25,5061 1054,5061 1103.75,5061 1153.5,5061 1203.25,5061 1255.25,5061 1305,5061 647.25,5062 697,5062 746.75,5062 796.5,5062 846.25,5062 898.25,5062 948,5062 289.25,5065 339,5065 388.75,5065 438.5,5065 488.25,5065 540.25,5065 590,5065 84.25,5066 134,5066 183.75,5066 233.5,5066 1004.25,5112 1054,5112 1103.75,5112 1153.5,5112 1203.25,5112 1255.25,5112 1305,5112 647.25,5113 697,5113 746.75,5113 796.5,5113 846.25,5113 898.25,5113 948,5113 289.25,5116 339,5116 388.75,5116 438.5,5116 488.25,5116 540.25,5116 590,5116 84.25,5117 134,5117 183.75,5117 233.5,5117 1004.25,5162 1054,5162 1103.75,5162 1153.5,5162 1203.25,5162 1255.25,5162 1305,5162 647.25,5163 697,5163 746.75,5163 796.5,5163 846.25,5163 898.25,5163 948,5163 289.25,5166 339,5166 388.75,5166 438.5,5166 488.25,5166 540.25,5166 590,5166 84.25,5167 134,5167 183.75,5167 233.5,5167 1004.25,5213 1054,5213 1103.75,5213 1153.5,5213 1203.25,5213 1255.25,5213 1305,5213 647.25,5214 697,5214 746.75,5214 796.5,5214 846.25,5214 898.25,5214 948,5214 289.25,5217 339,5217 388.75,5217 438.5,5217 488.25,5217 540.25,5217 590,5217 84.25,5218 134,5218 183.75,5218 233.5,5218 1004.25,5264 1054,5264 1103.75,5264 1153.5,5264 1203.25,5264 1255.25,5264 1305,5264 647.25,5265 697,5265 746.75,5265 796.5,5265 846.25,5265 898.25,5265 948,5265 289.25,5268 339,5268 388.75,5268 438.5,5268 488.25,5268 540.25,5268 590,5268 84.25,5269 134,5269 183.75,5269 233.5,5269 1004.25,5315 1054,5315 1103.75,5315 1153.5,5315 1203.25,5315 1255.25,5315 1305,5315 647.25,5316 697,5316 746.75,5316 796.5,5316 846.25,5316 898.25,5316 948,5316 289.25,5319 339,5319 388.75,5319 438.5,5319 488.25,5319 540.25,5319 590,5319 84.25,5320 134,5320 183.75,5320 233.5,5320 1004.25,5366 1054,5366 1103.75,5366 1153.5,5366 1203.25,5366 1255.25,5366 1305,5366 647.25,5367 697,5367 746.75,5367 796.5,5367 846.25,5367 898.25,5367 948,5367 289.25,5370 339,5370 388.75,5370 438.5,5370 488.25,5370 540.25,5370 590,5370 84.25,5371 134,5371 183.75,5371 233.5,5371 1004.25,5417 1054,5417 1103.75,5417 1153.5,5417 1203.25,5417 1255.25,5417 1305,5417 647.25,5418 697,5418 746.75,5418 796.5,5418 846.25,5418 898.25,5418 948,5418 289.25,5421 339,5421 388.75,5421 438.5,5421 488.25,5421 540.25,5421 590,5421 84.25,5422 134,5422 183.75,5422 233.5,5422 1004.25,5468 1054,5468 1103.75,5468 1153.5,5468 1203.25,5468 1255.25,5468 1305,5468 647.25,5469 697,5469 746.75,5469 796.5,5469 846.25,5469 898.25,5469 948,5469 289.25,5472 339,5472 388.75,5472 438.5,5472 488.25,5472 540.25,5472 590,5472 84.25,5473 134,5473 183.75,5473 233.5,5473 1004.25,5519 1054,5519 1103.75,5519 1153.5,5519 1203.25,5519 1255.25,5519 1305,5519 647.25,5520 697,5520 746.75,5520 796.5,5520 846.25,5520 898.25,5520 948,5520 289.25,5523 339,5523 388.75,5523 438.5,5523 488.25,5523 540.25,5523 590,5523 84.25,5524 134,5524 183.75,5524 233.5,5524 1004.25,5569 1054,5569 1103.75,5569 1153.5,5569 1203.25,5569 1255.25,5569 1305,5569 647.25,5570 697,5570 746.75,5570 796.5,5570 846.25,5570 898.25,5570 948,5570 289.25,5573 339,5573 388.75,5573 438.5,5573 488.25,5573 540.25,5573 590,5573 84.25,5574 134,5574 183.75,5574 233.5,5574 1004.25,5620 1054,5620 1103.75,5620 1153.5,5620 1203.25,5620 1255.25,5620 1305,5620 647.25,5621 697,5621 746.75,5621 796.5,5621 846.25,5621 898.25,5621 948,5621 289.25,5624 339,5624 388.75,5624 438.5,5624 488.25,5624 540.25,5624 590,5624 84.25,5625 134,5625 183.75,5625 233.5,5625 1004.25,5671 1054,5671 1103.75,5671 1153.5,5671 1203.25,5671 1255.25,5671 1305,5671 647.25,5672 697,5672 746.75,5672 796.5,5672 846.25,5672 898.25,5672 948,5672 289.25,5675 339,5675 388.75,5675 438.5,5675 488.25,5675 540.25,5675 590,5675 84.25,5676 134,5676 183.75,5676 233.5,5676 1004.25,5722 1054,5722 1103.75,5722 1153.5,5722 1203.25,5722 1255.25,5722 1305,5722 647.25,5723 697,5723 746.75,5723 796.5,5723 846.25,5723 898.25,5723 948,5723 289.25,5726 339,5726 388.75,5726 438.5,5726 488.25,5726 540.25,5726 590,5726 84.25,5727 134,5727 183.75,5727 233.5,5727 1003.5,5771 1053.25,5771 1103,5771 1152.75,5771 1202.5,5771 1254.5,5771 1304.25,5771 646.5,5772 696.25,5772 746,5772 795.75,5772 845.5,5772 897.5,5772 947.25,5772 288.5,5775 338.25,5775 388,5775 437.75,5775 487.5,5775 539.5,5775 589.25,5775 83.5,5776 133.25,5776 183,5776 232.75,5776 1003.5,5822 1053.25,5822 1103,5822 1152.75,5822 1202.5,5822 1254.5,5822 1304.25,5822 646.5,5823 696.25,5823 746,5823 795.75,5823 845.5,5823 897.5,5823 947.25,5823 288.5,5826 338.25,5826 388,5826 437.75,5826 487.5,5826 539.5,5826 589.25,5826 83.5,5827 133.25,5827 183,5827 232.75,5827 1003.5,5873 1053.25,5873 1103,5873 1152.75,5873 1202.5,5873 1254.5,5873 1304.25,5873 646.5,5874 696.25,5874 746,5874 795.75,5874 845.5,5874 897.5,5874 947.25,5874 288.5,5877 338.25,5877 388,5877 437.75,5877 487.5,5877 539.5,5877 589.25,5877 133.25,5878 183,5878 232.75,5878 1003.5,5924 1053.25,5924 1103,5924 1152.75,5924 1202.5,5924 1254.5,5924 1304.25,5924 646.5,5925 696.25,5925 746,5925 795.75,5925 845.5,5925 897.5,5925 947.25,5925 288.5,5928 338.25,5928 388,5928 437.75,5928 487.5,5928 539.5,5928 589.25,5928 183,5929 232.75,5929 1003.5,5974 1053.25,5974 1103,5974 1152.75,5974 1202.5,5974 1254.5,5974 1304.25,5974 646.5,5975 696.25,5975 746,5975 795.75,5975 845.5,5975 897.5,5975 947.25,5975 288.5,5978 338.25,5978 388,5978 437.75,5978 487.5,5978 539.5,5978 589.25,5978 232.75,5979
  other v3: 7068.52,1459.44 6158,4895 2558.76,5036.19 2587,5037 2614.12,5037 2558.52,5066.19 2586.76,5067 2615,5067.81
PWMA: J3.57 J16.20 J21.5 | length 2037.2
  Top Layer w8: J3.57@5430.13,5711 5430.13,5862.13 v2(5481,5913) 5481,6060 J16.20@5490,6069 ; v2(5580,5913) 5600.55,5892.45 6417.15,5892.45 6483.47,5826.13 7016.13,5826.13 J21.5@7075,5885
  Signal Layer 1 w8: v2(5481,5913) v2(5580,5913)
PWMB: J3.59 J16.22 J21.3 | length 1972.7
  Top Layer w8: J3.59@5398.64,5711 5398.64,5906.64 v2@5440,5948 ; J16.22@5440,6069 v2@5440,5948 ; v2(5441,5949) v2@5440,5948 ; v2(5581,5949) 5623.55,5906.45 6422.95,5906.45 6487.4,5842 6932,5842 J21.3@6975,5885
  Signal Layer 1 w8: v2(5441,5949) v2(5581,5949)
PWMC: J3.54 J16.16 J20.5 | length 3942.3
  Top Layer w8: J16.16@5590,6069 5590,6028 5556,5994 5556,5846 ; J3.54@5619.11,5577.14 5619.11,5598.89 5556,5662 5556,5846 ; J20.5@8756,5885 8706,5835 8706,5763 8624.13,5681.13 6712.08,5681.13 6595.08,5798.13 6471.87,5798.13 6405.55,5864.45 5627.86,5864.45 5609.42,5846 5556,5846
PWMD: J3.56 J16.18 J20.3 | length 3799.5
  Top Layer w8: J16.18@5540,6069 5530,6059 v2(5530,5878) 5530,5647 5587.61,5589.39 J3.56@5587.61,5577.14 ; v2(5582,5877) 5583.45,5878.45 6411.35,5878.45 6477.67,5812.13 6600.87,5812.13 6716,5697 8395,5697 8529,5831 8602,5831 J20.3@8656,5885
  Signal Layer 1 w8: v2(5530,5878) v2@5582,5878
PWME: J3.61 J16.24 U15.2 U15.4 U18.2 U18.4 | length 3418.4
  Top Layer w6: J3.61@5367.14,5711 5367.14,5671.86 5385,5654 5423.97,5654 5472.56,5605.41 5472.56,5352.56 5406,5286 v2(5406,5186)
  Top Layer w8: J3.61@5367.14,5711 5367.14,5947.14 5390,5970 J16.24@5390,6069
  Top Layer w20: U18.4@5557.42,4604.45 5557.42,4647.42 5575,4665 5640,4665 ; v2(5572,4982) 5657.42,4896.58 ; U18.2@5657.42,4604.45 5657.42,4647.58 ; U15.4@6479.39,4600.8 6479.39,4644.39 6498,4663 6563,4663 ; U15.2@6579.39,4600.8 6579.39,4646.61 ; 5640,4665 5657.42,4647.58 ; 5640,4665 5657.42,4665 ; 5640,4665 5657.42,4682.42 ; 5657.42,4647.58 5657.42,4665 ; 5657.42,4665 5657.42,4682.42 ; 5657.42,4682.42 5657.42,4896.58 ; 5657.42,4896.58 5775.08,4896.58 5880.5,5002 6549,5002 6579.39,4971.61 6579.39,4679.39 ; 6563,4663 6579.39,4646.61 ; 6563,4663 6579.39,4663 ; 6563,4663 6579.39,4679.39 ; 6579.39,4646.61 6579.39,4663 ; 6579.39,4663 6579.39,4679.39
  Signal Layer 1 w15: v2(5406,5186) 5406,5148 v2(5572,4982)
PWMF: J16.26 R12.2 R87.1 U14.2 U14.4 U17.2 U17.4 | length 9543.5
  Top Layer w8: v2(5366,5180.86) 5366,5382 R87.1@5367,5383
  Top Layer w20: v3(3980,4046) 3980,4319 4243,4582 4899,4582 v2(5366,5049) ; v3(4188,2090) 4188,1834.96 5038.52,984.44 5723.47,984.44 ; v2(5330,5446) R12.2@5367.01,5446 R87.1@5367,5383 ; v2(5340,5993) J16.26@5340,6069 ; U14.2@5742.47,1499.79 5742.47,1457.44 ; U14.4@5842.47,1499.79 5842.47,1458.39 5823.52,1439.44 5760.47,1439.44 ; U17.2@6639.91,1506.95 6639.91,1457.44 ; U17.4@6739.91,1506.95 6739.91,1459.83 6716.52,1436.44 6660.91,1436.44 ; 5723.47,984.44 5741.52,984.44 ; 5723.47,984.44 5742.47,1003.44 ; 5741.52,984.44 5761.47,984.44 ; 5741.52,984.44 5742.47,985.39 5742.47,1003.44 ; 5742.47,1003.44 5742.47,1421.44 ; 5742.47,1003.44 5761.47,984.44 ; 5742.47,1421.44 5742.47,1439.44 ; 5742.47,1421.44 5760.47,1439.44 ; 5742.47,1439.44 5760.47,1439.44 ; 5742.47,1439.44 5742.47,1457.44 ; 5742.47,1457.44 5760.47,1439.44 ; 5761.47,984.44 6434.52,984.44 6639.91,1189.83 6639.91,1415.44 ; 6639.91,1415.44 6639.91,1436.44 ; 6639.91,1415.44 6660.91,1436.44 ; 6639.91,1436.44 6660.91,1436.44 ; 6639.91,1436.44 6639.91,1457.44 ; 6639.91,1457.44 6660.91,1436.44
  Signal Layer 1 w8: v2(5330,5446) 5330,5510 5340,5520 v2(5340,5993) ; v2(5366,5049) v2(5366,5180.86)
  Signal Layer 2 w20: v3(3980,4046) 3980,4011 4217,3774 4217,2122 4185,2090 4185,2088 4187,2090 v3(4188,2090)
S_1: J5.1 Q1.3 R25.1 | length 845.4
  Top Layer w20: Q1.3@7347,6348.89 7360.56,6335.33 R25.1@7360.56,6215 7372,6215 7435,6152 J5.1@7435,5966
  Signal Layer 2 w60: Q1.3@7347,6348.89 7347,6054 J5.1@7435,5966
S_2: J7.1 Q16.3 R71.1 | length 838.5
  Top Layer w20: Q16.3@8099.44,6348.89 8121.56,6326.78 R71.1@8121.56,6216 8124.76,6216 8185,6155.76 J7.1@8185,5966
  Signal Layer 2 w60: Q16.3@8099.44,6348.89 8099.44,6051.56 J7.1@8185,5966
S_3: J10.1 Q2.3 R26.1 | length 728.8
  Top Layer w20: Q2.3@9001.89,6348.89 9017.56,6333.22 R26.1@9017.56,6215 9019.76,6215 9116,6118.76 J10.1@9116,5966
  Signal Layer 2 w60: 9001.89,6051.56 Q2.3@9001.89,6348.89
S_4: J12.1 Q17.3 R72.1 | length 728.1
  Top Layer w20: Q17.3@9754.33,6348.89 9770.12,6333.11 R72.1@9770.12,6216 9772.88,6216 9866,6122.88 J12.1@9866,5966
  Signal Layer 2 w60: 9754.33,6051.56 Q17.3@9754.33,6348.89
SR1_1: R152.2 R158.2 SR5.1 | length 197.8
  Top Layer w30: SR5.1@5585.1,1926.05 5679.31,1831.83 R158.2@5687.47,1831.83 R152.2@5743.92,1831.83
SR1_2: R155.2 R157.2 SR6.1 | length 213.4
  Top Layer w20: R155.2@5863.92,1834.63 R157.2@5923.92,1834.63 5954.71,1834.63 6035,1914.92 SR6.1@6035,1924
SR1_3: R168.2 R173.2 SR7.1 | length 170.3
  Top Layer w30: SR7.1@6484.9,1926.05 6554.99,1855.96 R173.2@6554.99,1841.55 R168.2@6611.76,1841.55
SR1_4: R170.2 R172.2 SR8.1 | length 250.6
  Top Layer w30: R170.2@6738.74,1834.66 R172.2@6795.5,1834.66 6873.74,1834.66 6934.8,1895.72 SR8.1@6934.8,1924.95
SR2_1: R153.2 R160.2 SR1.1 | length 205.6
  Top Layer w15: R160.2@6625.58,4261.86 R160.2@6627.19,4260.24
  Top Layer w30: R153.2@6567.19,4261.86 R160.2@6625.58,4261.86 ; R160.2@6627.19,4260.24 6642.82,4260.24 SR1.1@6734.28,4168.79
SR2_2: R156.2 R159.2 SR2.1 | length 211.1
  Top Layer w15: SR2.1@6284.38,4168.79 SR2.1@6284.38,4183.38
  Top Layer w30: SR2.1@6284.38,4183.38 6284.38,4193.96 6353.46,4263.04 R159.2@6386.88,4263.04 R156.2@6441.7,4263.04
SR2_3: R169.2 R175.2 SR3.1 | length 225.5
  Top Layer w15: R175.2@5715.66,4274 R175.2@5717.54,4275.88 ; SR3.1@5824.63,4168.79 SR3.1@5834.48,4168.79
  Top Layer w30: R169.2@5664,4274 R175.2@5715.66,4274 ; R175.2@5717.54,4275.88 5727.39,4275.88 SR3.1@5834.48,4168.79
SR2_4: R171.2 R174.2 SR4.1 | length 234.5
  Top Layer w30: SR4.1@5384.58,4168.79 5384.58,4221.58 5435.33,4272.33 R174.2@5485.22,4272.33 R171.2@5545.22,4272.33
Temp1: C58.1 J3.26 J16.3 U7.3 | length 4069.5
  Top Layer w8: U7.3@8043,4857 8144.43,4857 C58.1@8148,4853.43
  Top Layer w15: v2(6060.06,5469.2) J3.26@6060.06,5577.14
  Top Layer w25: v2(5890,6155) J16.3@5890,6229
  Signal Layer 1 w8: v2(5890,6155) 5820,6085 5666,6085 5617,6036 5617,5984.8 6060.06,5541.74 v2(6060.06,5469.2)
  Signal Layer 2 w8: v2(5890,6155) 6285.07,6155 6320.07,6120 6320.07,6089.68 7552.75,4857 U7.3@8043,4857
Temp2: C59.1 J3.23 J16.4 U8.3 | length 3857.7
  Top Layer w8: J3.23@6091.55,5711 v2(6091.55,5841.45) ; v2(6347,5265) 6401,5211 8282.57,5211 C59.1@8725.57,4768 8729,4764.57 U8.3@8729,4648
  Top Layer w25: v2(5890,5995) J16.4@5890,6069
  Signal Layer 1 w8: v2(5890,5995) 5973,5912 6021,5912 v2(6091.55,5841.45) 6320.52,5612.48 6320.52,5609.99 6347,5583.51 v2(6347,5265)
Vfb_Io: J3.20 J16.12 J18.5 R91.2 U9.8 | length 5274.3
  Top Layer w8: U9.8@3441.8,4094.61 3420.18,4073 3279,4073 3222,4130 J18.5@3222,4449 3511,4738 3926,4738 4295,5107 6106,5107 v2(6180,5181) ; R91.2@6138.5,5441 6154.54,5457.04 J3.20@6154.54,5577.14
  Top Layer w15: J3.20@6154.54,5577.14 v2(6154.54,5619.52)
  Top Layer w25: v2(5690,5995) J16.12@5690,6069
  Signal Layer 1 w8: v2(5690,5995) 5828,5857 5987,5857 6154.54,5689.46 v2(6154.54,5619.52) 6267.5,5506.57 6267.5,5268.5 v2(6180,5181)
Vfb_Io2: J16.14 R92.2 U10.1 | length 4481.8
  Top Layer w8: U10.1@3500.87,4312.4 3492.6,4312.4 3474,4331 3474,4621 3498,4645 3860,4645 4308,5093 6147,5093 6207,5153 R92.2@6207,5313.5 v2(6244.5,5313.5)
  Top Layer w25: v2(5640,5995) J16.14@5640,6069
  Signal Layer 1 w8: v2(5640,5995) 6244.5,5390.5 v2(6244.5,5313.5)
Vfb_Vo: C39.1 J3.34 J16.8 R57.1 R63.2 | length 2784.1
  Top Layer w8: C39.1@4686.13,4943 4813.13,5070 v2(5275,5070) ; v2(5464,5292) 5585.57,5413.57 5887.57,5413.57 5934.07,5460.07 J3.34@5934.07,5577.14
  Top Layer w15: J3.34@5934.07,5577.14 v2(5934.07,5619.52)
  Top Layer w20: R57.1@4624,4873 R63.2@4691,4873 4691,4938.13 C39.1@4686.13,4943
  Top Layer w25: J16.8@5790,6069 v2(5790,6143)
  Signal Layer 1 w8: v2(5275,5070) 5275,5270 5297,5292 v2(5464,5292) ; v2(5790,6143) 5646,6143 5591,6088 5591,5974.07 5934.07,5631 v2(5934.07,5619.52)
Vfb_Vo2: C40.1 J3.12 J16.10 R42.1 R86.2 | length 3234
  Top Layer w8: C40.1@4688.57,4737 4688.57,4733.43 4759,4663 4826,4663 5111,4948 5196,4948 5320,5072 6177,5072 v2(6283,5178)
  Top Layer w15: J3.12@6280.53,5577.14 v2(6280.53,5619.52)
  Top Layer w20: R42.1@4624.5,4808 R86.2@4691,4808 4691,4739.43 C40.1@4688.57,4737
  Top Layer w25: v2(5740,5995) J16.10@5740,6069
  Signal Layer 1 w8: v2(5740,5995) 5855,5880 6020.05,5880 v2(6280.53,5619.52) 6283,5617.05 v2(6283,5178)
VIN_N: J16.2 R82.1 U5.6 | length 6537.6
  Top Layer w8: v2(5333,5205.5) 5325,5213.5 4449.5,5213.5 3789,5874 3074.37,5874 3021,5927.37 3021,6040 3004,6057 U5.6@3004,6096.43 3004,6120 3045,6161 3212.66,6161 3316.66,6057 4213.37,6057 4501.37,6345 5981.63,6345 6025,6301.63 6025,6162.37 6003.63,6141 5971,6141 5944,6114 5944,6073 J16.2@5940,6069 ; v2(5439,5205.5) 5447,5213.5 5511.5,5213.5 R82.1@5535,5190
  Signal Layer 1 w8: v2(5333,5205.5) 5341,5213.5 5431,5213.5 v2(5439,5205.5)
VIN_P: J16.1 R85.1 U5.7 | length 6410.8
  Top Layer w8: v2(5333,5237.5) 5325,5229.5 4456.13,5229.5 3795.63,5890 3081,5890 3037,5934 3037,6040 3054,6057 U5.7@3054,6096.43 3054,6135.87 3063.13,6145 3206.03,6145 3310.03,6041 4220,6041 4508,6329 5975,6329 6009,6295 6009,6169 5997,6157 5971,6157 5944,6184 5944,6225 J16.1@5940,6229 ; v2(5439,5237.5) 5447,5229.5 5511.5,5229.5 R85.1@5535,5253
  Signal Layer 1 w8: v2(5333,5237.5) 5341,5229.5 5431,5229.5 v2(5439,5237.5)
Vpri: C54.1 J3.30 R83.2 | length 324.7
  Top Layer w8: J3.30@5997.06,5577.14 5997.06,5421.43 C54.1@6070.5,5348 6133.5,5348 R83.2@6135,5346.5
pads on no net: D5. D20. J3.13 J3.16 J3.29 J3.32 J3.41 J3.43 J3.44 J3.66 J3.113 J3.114 J3.115 J3.116 J3.181 J3.182 J3.185 J3.186 J8.6 J14.61 J14.62 J14.136 J14.171 J14.172 J14.173 J14.174 J14.175 J14.176 J14.177 J14.178 L2.3 LBL1.0 Q1. Q2. Q16. Q17. SR1. SR2. SR3. SR4. SR5. SR6. SR7. SR8. T1.1 T1.3 T1.5 T1.6 T1.7 T1.8 T1.9 T1.10 T8.1 T8.3 T8.5 T8.6 T8.7 T8.8 T8.9 T8.10 U3.2 U7. U9.1 U14.1 U14.8 U15.1 U15.8 U17.1 U17.8 U18.1 U18.8

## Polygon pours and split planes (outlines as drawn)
12Vout on Signal Layer 2 "SIGNAL_LAYER_2_12VOUT_P455" (solid, remove dead copper, pour order 455): 4069,1723 4027,1681 2732,1681 2626,1787 2626,3947 2705,4026 3817,4026 4069,3774
NetD5_2 on Signal Layer 2 "SIGNAL_LAYER_2_NETD5_2_P439" (solid, remove dead copper, pour order 439): 9736,6979 11001,6979 11166,7144 11166,7936 10916,8186 9370,8186 9200,8016 9200,7625 9088,7513 7982,7513 7743,7274 7743,7021 7785,6979
Dbus+ on Signal Layer 2 "SIGNAL_LAYER_2_DBUS+_P435" (solid, remove dead copper, pour order 435): 3014.5,6952 3014.5,7226 3282.5,7494 6798,7494 6990.5,7301.5 6990.5,7032 6961.5,7003 6056,7003 5957,6904 3021.5,6904 3015.5,6910 3015.5,6951
Batt- on Signal Layer 2 "SIGNAL_LAYER_2_BATT-_P419" (solid, pour order 419): 282,6891 282,6720 292,6710 1166,6710 1182,6726 1182,6918 796,7304 596,7304 572,7280 572,7178 281,6887 280,6887
NetC5_1 on Signal Layer 2 "SIGNAL_LAYER_2_NETC5_1_P415" (solid, remove dead copper, pour order 415): 567,7591 567,7561 600,7528 1139,7528 1209,7598 1209,8300 1156,8353 1012,8353 967,8308 967,7994 570,7597 569,7597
